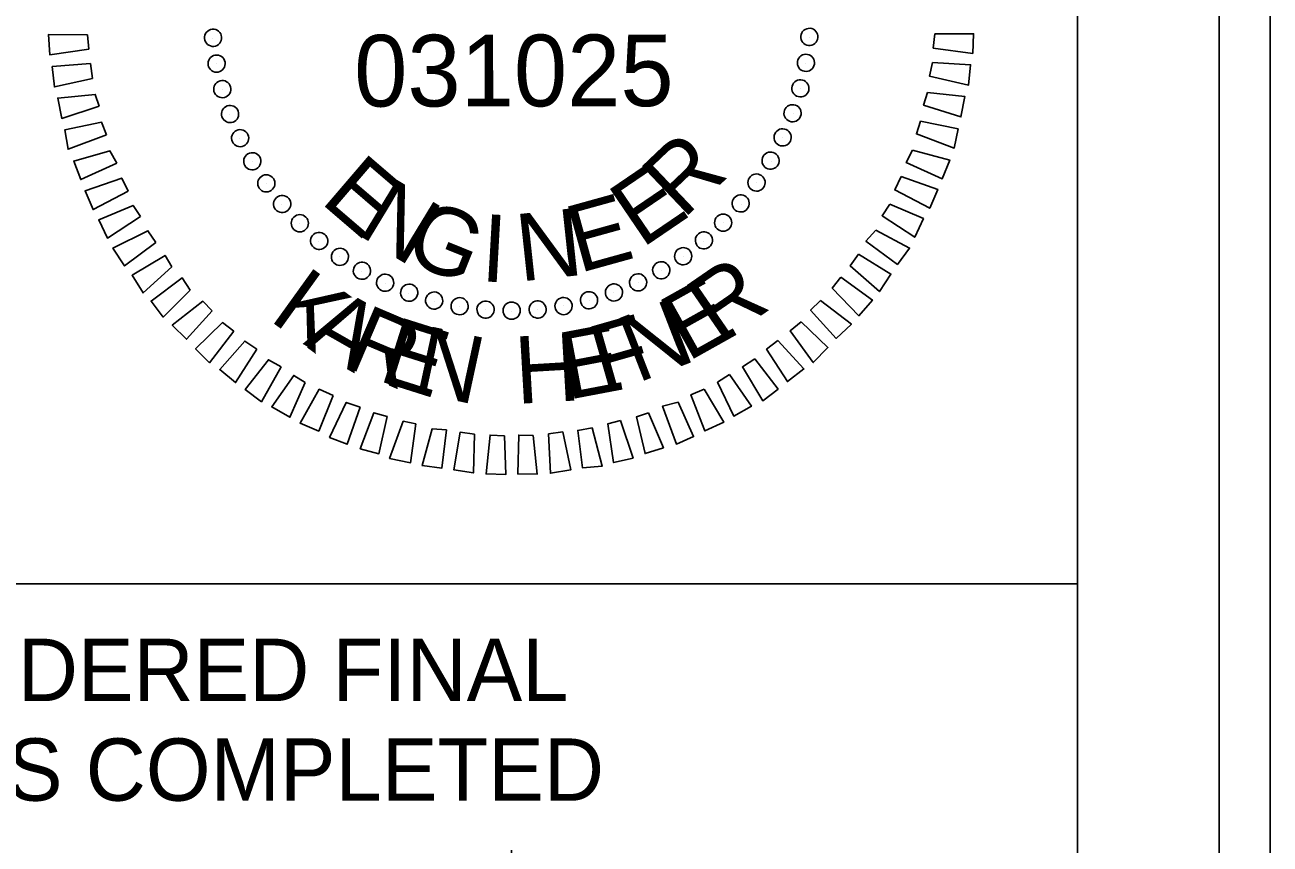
# Model space of a CAD drawing. Extents: x 2331575 to 2333259, y 609001 to 610101.
# Drawn here: x 2333149.3 to 2333259.2, y 609916 to 609988.3 of the extents above; entities that cross this region are included whole.
import ezdxf

# ---------------------------------------------------------------- set-up
doc = ezdxf.new("R2010")
doc.units = 0
for name, color, linetype in [('Default', 7, 'Continuous'), ('Sheet Plot Border Inside CELL', 7, 'Continuous'), ('Sheet Plot Border Outside CELL', 7, 'Continuous'), ('Sheet Profile CELL', 7, 'Continuous'), ('Sheet Profile Grid Major CELL', 7, 'Continuous'), ('Sheet Sticker Exception Certification CELL', 7, 'Continuous')]:
    doc.layers.add(name, color=color, linetype=linetype)

msp = doc.modelspace()

# ---------------------------------------------------------------- linework, layer by layer
at = {"layer": 'Default'}
for p, q in [((2333165.87, 609987.06), (2333165.87, 609987.06)), ((2333165.87, 609987.06), (2333165.87, 609987.06)), ((2333218.56, 609987.16), (2333218.56, 609987.16)), ((2333218.56, 609987.16), (2333218.56, 609987.16)), ((2333166.23, 609984.85), (2333166.23, 609984.85)), ((2333166.23, 609984.85), (2333166.23, 609984.85)), ((2333218.24, 609984.89), (2333218.24, 609984.89)), ((2333218.24, 609984.89), (2333218.24, 609984.89)), ((2333166.7, 609982.54), (2333166.7, 609982.54)), ((2333166.7, 609982.54), (2333166.7, 609982.54)), ((2333217.8, 609982.67), (2333217.8, 609982.67)), ((2333217.8, 609982.67), (2333217.8, 609982.67)), ((2333167.37, 609980.34), (2333167.37, 609980.34)), ((2333167.37, 609980.34), (2333167.37, 609980.34)), ((2333217.11, 609980.44), (2333217.11, 609980.44)), ((2333217.11, 609980.44), (2333217.11, 609980.44)), ((2333168.25, 609978.2), (2333168.25, 609978.2)), ((2333168.25, 609978.2), (2333168.25, 609978.2)), ((2333216.2, 609978.31), (2333216.2, 609978.31)), ((2333216.2, 609978.31), (2333216.2, 609978.31)), ((2333169.34, 609976.22), (2333169.34, 609976.22)), ((2333169.34, 609976.22), (2333169.34, 609976.22)), ((2333215.18, 609976.24), (2333215.18, 609976.24)), ((2333215.18, 609976.24), (2333215.18, 609976.24)), ((2333170.59, 609974.24), (2333170.59, 609974.24)), ((2333170.59, 609974.24), (2333170.59, 609974.24)), ((2333213.9, 609974.32), (2333213.9, 609974.32)), ((2333213.9, 609974.32), (2333213.9, 609974.32)), ((2333171.94, 609972.42), (2333171.94, 609972.42)), ((2333171.94, 609972.42), (2333171.94, 609972.42)), ((2333212.52, 609972.39), (2333212.52, 609972.39)), ((2333212.52, 609972.39), (2333212.52, 609972.39)), ((2333173.56, 609970.71), (2333173.56, 609970.71)), ((2333173.56, 609970.71), (2333173.56, 609970.71)), ((2333210.97, 609970.78), (2333210.97, 609970.78)), ((2333210.97, 609970.78), (2333210.97, 609970.78)), ((2333175.17, 609969.16), (2333175.17, 609969.16)), ((2333175.17, 609969.16), (2333175.17, 609969.16)), ((2333209.21, 609969.17), (2333209.21, 609969.17)), ((2333209.21, 609969.17), (2333209.21, 609969.17)), ((2333177.09, 609967.78), (2333177.09, 609967.78)), ((2333177.09, 609967.78), (2333177.09, 609967.78)), ((2333207.44, 609967.82), (2333207.44, 609967.82)), ((2333207.44, 609967.82), (2333207.44, 609967.82)), ((2333205.46, 609966.57), (2333205.46, 609966.57)), ((2333205.46, 609966.57), (2333205.46, 609966.57)), ((2333179.01, 609966.49), (2333179.01, 609966.49)), ((2333179.01, 609966.49), (2333179.01, 609966.49)), ((2333203.43, 609965.48), (2333203.43, 609965.48)), ((2333203.43, 609965.48), (2333203.43, 609965.48)), ((2333181.09, 609965.43), (2333181.09, 609965.43)), ((2333181.09, 609965.43), (2333181.09, 609965.43)), ((2333183.16, 609964.52), (2333183.16, 609964.52)), ((2333183.16, 609964.52), (2333183.16, 609964.52)), ((2333201.28, 609964.6), (2333201.28, 609964.6)), ((2333201.28, 609964.6), (2333201.28, 609964.6)), ((2333185.44, 609963.88), (2333185.44, 609963.88)), ((2333185.44, 609963.88), (2333185.44, 609963.88)), ((2333187.66, 609963.44), (2333187.66, 609963.44)), ((2333187.66, 609963.44), (2333187.66, 609963.44)), ((2333196.83, 609963.46), (2333196.83, 609963.46)), ((2333196.83, 609963.46), (2333196.83, 609963.46)), ((2333199.13, 609963.92), (2333199.13, 609963.92)), ((2333199.13, 609963.92), (2333199.13, 609963.92)), ((2333189.93, 609963.12), (2333189.93, 609963.12)), ((2333189.93, 609963.12), (2333189.93, 609963.12)), ((2333192.25, 609963), (2333192.25, 609963)), ((2333192.25, 609963), (2333192.25, 609963)), ((2333194.57, 609963.1), (2333194.57, 609963.1)), ((2333194.57, 609963.1), (2333194.57, 609963.1))]:
    msp.add_line(p, q, dxfattribs=at)
for points in [[(2333229.62, 609987.47), (2333233.05, 609987.48), (2333232.97, 609985.74), (2333229.49, 609986.21)], [(2333154.93, 609986.12), (2333151.46, 609985.63), (2333151.37, 609987.42), (2333154.8, 609987.38)], [(2333155.24, 609983.54), (2333151.88, 609982.79), (2333151.69, 609984.58), (2333155.06, 609984.85)], [(2333229.41, 609984.94), (2333232.78, 609984.74), (2333232.6, 609982.95), (2333229.16, 609983.72)], [(2333155.82, 609981.08), (2333152.52, 609980.01), (2333152.17, 609981.8), (2333155.48, 609982.12)], [(2333228.98, 609982.3), (2333232.26, 609981.94), (2333231.92, 609980.14), (2333228.63, 609981.18)], [(2333228.35, 609979.75), (2333231.68, 609979.08), (2333231.34, 609977.39), (2333228, 609978.64)], [(2333156.49, 609978.56), (2333153.09, 609977.28), (2333152.8, 609979.01), (2333156.05, 609979.66)], [(2333157.39, 609976.05), (2333154.2, 609974.61), (2333153.59, 609976.24), (2333156.78, 609977.14)], [(2333227.65, 609977.21), (2333230.94, 609976.33), (2333230.28, 609974.68), (2333227.1, 609976.1)], [(2333158.38, 609973.59), (2333155.3, 609971.95), (2333154.58, 609973.62), (2333157.83, 609974.74)], [(2333226.64, 609974.87), (2333229.88, 609973.73), (2333229.17, 609972.08), (2333226.09, 609973.7)], [(2333159.47, 609971.34), (2333156.56, 609969.44), (2333155.79, 609971.06), (2333158.82, 609972.33)], [(2333225.64, 609972.43), (2333228.61, 609971.17), (2333227.85, 609969.52), (2333224.97, 609971.42)], [(2333160.84, 609969.05), (2333158.08, 609966.99), (2333157.05, 609968.56), (2333160.13, 609970.09)], [(2333224.42, 609970.14), (2333227.4, 609968.56), (2333226.32, 609967.12), (2333223.54, 609969.18)], [(2333162.25, 609966.91), (2333159.71, 609964.6), (2333158.73, 609966.16), (2333161.65, 609967.91)], [(2333222.88, 609968.01), (2333225.75, 609966.27), (2333224.73, 609964.72), (2333222.16, 609966.99)], [(2333163.87, 609964.84), (2333161.49, 609962.47), (2333160.41, 609963.88), (2333163.16, 609965.93)], [(2333221.33, 609965.98), (2333224.11, 609963.97), (2333222.92, 609962.58), (2333220.56, 609965.01)], [(2333165.8, 609963.03), (2333163.53, 609960.51), (2333162.29, 609961.75), (2333164.99, 609963.86)], [(2333219.53, 609963.94), (2333222.25, 609961.83), (2333220.91, 609960.59), (2333218.65, 609963.08)], [(2333167.73, 609961.22), (2333165.57, 609958.44), (2333164.34, 609959.68), (2333166.71, 609961.99)], [(2333217.83, 609962.06), (2333220.18, 609959.79), (2333218.89, 609958.45), (2333216.84, 609961.25)], [(2333169.76, 609959.63), (2333167.87, 609956.69), (2333166.48, 609957.83), (2333168.69, 609960.35)], [(2333215.75, 609960.39), (2333218.06, 609957.9), (2333216.61, 609956.77), (2333214.76, 609959.63)], [(2333171.9, 609958.09), (2333170.16, 609955), (2333168.72, 609956.08), (2333170.78, 609958.7)], [(2333213.72, 609958.77), (2333215.78, 609956.12), (2333214.42, 609955.09), (2333212.63, 609958.07)], [(2333174.03, 609956.7), (2333172.67, 609953.62), (2333171.07, 609954.54), (2333173.02, 609957.32)], [(2333211.48, 609957.41), (2333213.43, 609954.6), (2333211.87, 609953.73), (2333210.44, 609956.71)], [(2333176.48, 609955.54), (2333175.22, 609952.41), (2333173.57, 609953.11), (2333175.26, 609956.1)], [(2333209.24, 609956.1), (2333210.99, 609953.19), (2333209.31, 609952.42), (2333208.09, 609955.61)], [(2333178.87, 609954.53), (2333177.72, 609951.24), (2333176.18, 609951.84), (2333177.65, 609954.93)], [(2333206.95, 609954.95), (2333208.32, 609951.92), (2333206.81, 609951.26), (2333205.58, 609954.61)], [(2333181.26, 609953.68), (2333180.53, 609950.4), (2333178.89, 609950.84), (2333180.09, 609954.03)], [(2333204.33, 609954.01), (2333205.65, 609950.93), (2333204.03, 609950.42), (2333203.28, 609953.67)], [(2333183.8, 609953.04), (2333183.33, 609949.61), (2333181.48, 609949.99), (2333182.68, 609953.28)], [(2333186.49, 609952.51), (2333186.08, 609949.13), (2333184.34, 609949.36), (2333185.23, 609952.6)], [(2333188.98, 609952.14), (2333188.88, 609948.71), (2333187.14, 609949), (2333187.71, 609952.32)], [(2333196.77, 609952.34), (2333197.47, 609948.98), (2333195.68, 609948.68), (2333195.51, 609952.16)], [(2333199.35, 609952.7), (2333200.26, 609949.3), (2333198.52, 609949.16), (2333198.09, 609952.47)], [(2333201.87, 609953.33), (2333202.98, 609950.03), (2333201.25, 609949.63), (2333200.76, 609953.05)], [(2333191.62, 609951.98), (2333191.73, 609948.56), (2333189.99, 609948.63), (2333190.35, 609952.06)], [(2333194.14, 609952.03), (2333194.52, 609948.61), (2333192.79, 609948.63), (2333192.88, 609952.06)]]:
    msp.add_lwpolyline(points, close=True, dxfattribs=at)
for centre, major_axis in [((2333165.89, 609987.12), (-0.756, -0.067)), ((2333218.54, 609987.2), (0.756, -0.065)), ((2333166.2, 609984.84), (-0.747, -0.133)), ((2333218.24, 609984.91), (0.747, -0.131)), ((2333166.7, 609982.59), (-0.733, -0.197)), ((2333217.75, 609982.66), (0.733, -0.195)), ((2333167.39, 609980.39), (-0.713, -0.26)), ((2333217.06, 609980.46), (0.713, -0.258)), ((2333168.28, 609978.26), (-0.687, -0.322)), ((2333216.18, 609978.33), (0.688, -0.32)), ((2333169.35, 609976.22), (-0.656, -0.38)), ((2333215.12, 609976.28), (0.658, -0.378)), ((2333170.59, 609974.27), (-0.621, -0.436)), ((2333213.88, 609974.34), (0.622, -0.434)), ((2333171.99, 609972.45), (-0.58, -0.488)), ((2333212.48, 609972.5), (0.582, -0.487)), ((2333173.55, 609970.75), (-0.536, -0.537)), ((2333210.93, 609970.8), (0.537, -0.536)), ((2333175.26, 609969.19), (-0.487, -0.582)), ((2333209.23, 609969.24), (0.488, -0.58)), ((2333177.09, 609967.79), (-0.434, -0.622)), ((2333207.4, 609967.84), (0.436, -0.621)), ((2333179.03, 609966.56), (-0.378, -0.658)), ((2333205.46, 609966.6), (0.38, -0.656)), ((2333181.08, 609965.5), (-0.32, -0.688)), ((2333183.21, 609964.62), (-0.258, -0.713)), ((2333201.29, 609964.64), (0.26, -0.713)), ((2333203.42, 609965.53), (0.322, -0.687)), ((2333185.41, 609963.93), (-0.195, -0.733)), ((2333199.09, 609963.95), (0.197, -0.733)), ((2333187.66, 609963.43), (-0.131, -0.747)), ((2333189.95, 609963.13), (-0.065, -0.756)), ((2333192.25, 609963.04), (0.001, -0.759)), ((2333194.55, 609963.14), (0.067, -0.756)), ((2333196.84, 609963.44), (0.133, -0.747))]:
    msp.add_ellipse(centre, major_axis=major_axis, ratio=0.999708, dxfattribs=at)
at = {"layer": 'Sheet Plot Border Inside CELL'}
msp.add_lwpolyline([(2331588.23, 609023.93), (2333254.73, 609023.93), (2333254.73, 610079.03), (2331588.23, 610079.03)], close=True, dxfattribs=at)
at = {"layer": 'Sheet Plot Border Outside CELL'}
msp.add_lwpolyline([(2331575.23, 609001.48), (2333259.23, 609001.48), (2333259.23, 610101.48), (2331575.23, 610101.48)], close=True, dxfattribs=at)
at = {"layer": 'Sheet Profile CELL'}
for points in [[(2333242.23, 610076.48), (2331742.23, 610076.48), (2331742.23, 609026.48), (2333242.23, 609026.48)], [(2333142.23, 610051.43), (2333242.23, 610051.43), (2333242.23, 609938.93), (2333142.23, 609938.93)]]:
    msp.add_lwpolyline(points, close=True, dxfattribs=at)
at = {"layer": 'Sheet Profile Grid Major CELL'}
msp.add_lwpolyline([(2333192.23, 609915.43), (2333192.23, 609576.48), (2333242.23, 609576.48), (2333242.23, 609926.48)], dxfattribs=at)
at = {"layer": 'Sheet Sticker Exception Certification CELL'}
for p, q in [((2333042.18, 609938.93), (2333242.21, 609938.93)), ((2333042.18, 609938.93), (2333242.21, 609938.93)), ((2333242.21, 609938.92), (2333242.21, 609915.42)), ((2333242.21, 609938.92), (2333242.21, 609915.42))]:
    msp.add_line(p, q, dxfattribs=at)

# ---------------------------------------------------------------- texts
at = {"layer": 'Default'}
for s, height, rotation, p in [('031025', 6.322, 0.081, (2333178.35, 609981.05)), ('R', 5.94, 43.5624, (2333207.38, 609971.03)), ('E', 5.94, 319.3578, (2333175.26, 609972.64)), ('E', 5.94, 34.205, (2333203.74, 609968.49)), ('N', 5.94, 328.7149, (2333178.47, 609969.86)), ('E', 5.94, 15.4927, (2333198.19, 609966.33)), ('G', 5.94, 338.0712, (2333182.52, 609967.56)), ('N', 5.94, 6.1373, (2333192.99, 609965.6)), ('I', 5.94, 356.7822, (2333189.46, 609965.64)), ('K', 5.94, 324.2363, (2333170.74, 609962.26)), ('R', 5.94, 34.4906, (2333210.56, 609960.04)), ('E', 5.94, 29.2101, (2333207.78, 609958.48)), ('A', 5.94, 330.3893, (2333173.78, 609960.11)), ('R', 5.94, 336.9555, (2333177.26, 609958.2)), ('N', 5.94, 21.2433, (2333203.34, 609956.62)), ('E', 5.94, 342.5116, (2333180.35, 609956.89)), ('F', 5.94, 16.0317, (2333200.31, 609955.75)), ('N', 5.94, 347.7922, (2333183.4, 609955.94)), ('E', 5.94, 10.7511, (2333197.17, 609955.15)), ('H', 5.94, 3.3354, (2333192.7, 609954.8))]:
    msp.add_text(s, height=height, rotation=rotation, dxfattribs=at).set_placement(p)
at = {"layer": 'Sheet Sticker Exception Certification CELL'}
for s, p in [('DOCUMENT NOT CONSIDERED FINAL', (2333063.25, 609928.58)), ('DOCUMENT NOT CONSIDERED FINAL', (2333063.25, 609928.58)), ('UNLESS ALL SIGNATURES COMPLETED', (2333058.18, 609919.78)), ('UNLESS ALL SIGNATURES COMPLETED', (2333058.18, 609919.78))]:
    msp.add_text(s, height=5.5, dxfattribs=at).set_placement(p)

doc.saveas('drawing.dxf')
